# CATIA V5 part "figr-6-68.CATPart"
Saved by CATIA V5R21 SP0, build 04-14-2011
Part number: Part1
Bounding box of the stored display mesh (mm): x -44.666 to 44.666, y -69.79 to 69.79, z 0 to 74
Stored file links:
  D:\CATIA V5R21 E-RESOURCES\CATIA-V5R21\catia-v5r21-prt\c06-catia-v5r21-prt\c06-catia-v5r21-figr-6-68.CATPart
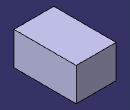
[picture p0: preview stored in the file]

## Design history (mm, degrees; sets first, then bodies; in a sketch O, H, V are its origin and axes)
Body1 (main body)
  Sketch1 on xy-plane, origin (0, 0, 0), H (1, 0, 0), V (0, 1, 0)
    line L1 (44.6658, 69.7903) -> (44.6658, -69.7903)
    line L2 (44.6658, -69.7903) -> (-44.6658, -69.7903)
    line L3 (-44.6658, -69.7903) -> (-44.6658, 69.7903)
    line L4 (-44.6658, 69.7903) -> (44.6658, 69.7903)
    vertical: L1 V, L3 V
    horizontal: L2 H, L4 H
    equidistance: L1 L3 O, L2 L4 O
  Pad1: profile Sketch1, direction (0, 0, 1), length 74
